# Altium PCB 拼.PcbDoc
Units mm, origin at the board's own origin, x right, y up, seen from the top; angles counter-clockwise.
Board outline 100.51 x 100 mm, 2 copper layers (Top Layer, Bottom Layer); 58 components, 0 nets, 318 pads, 0 vias.
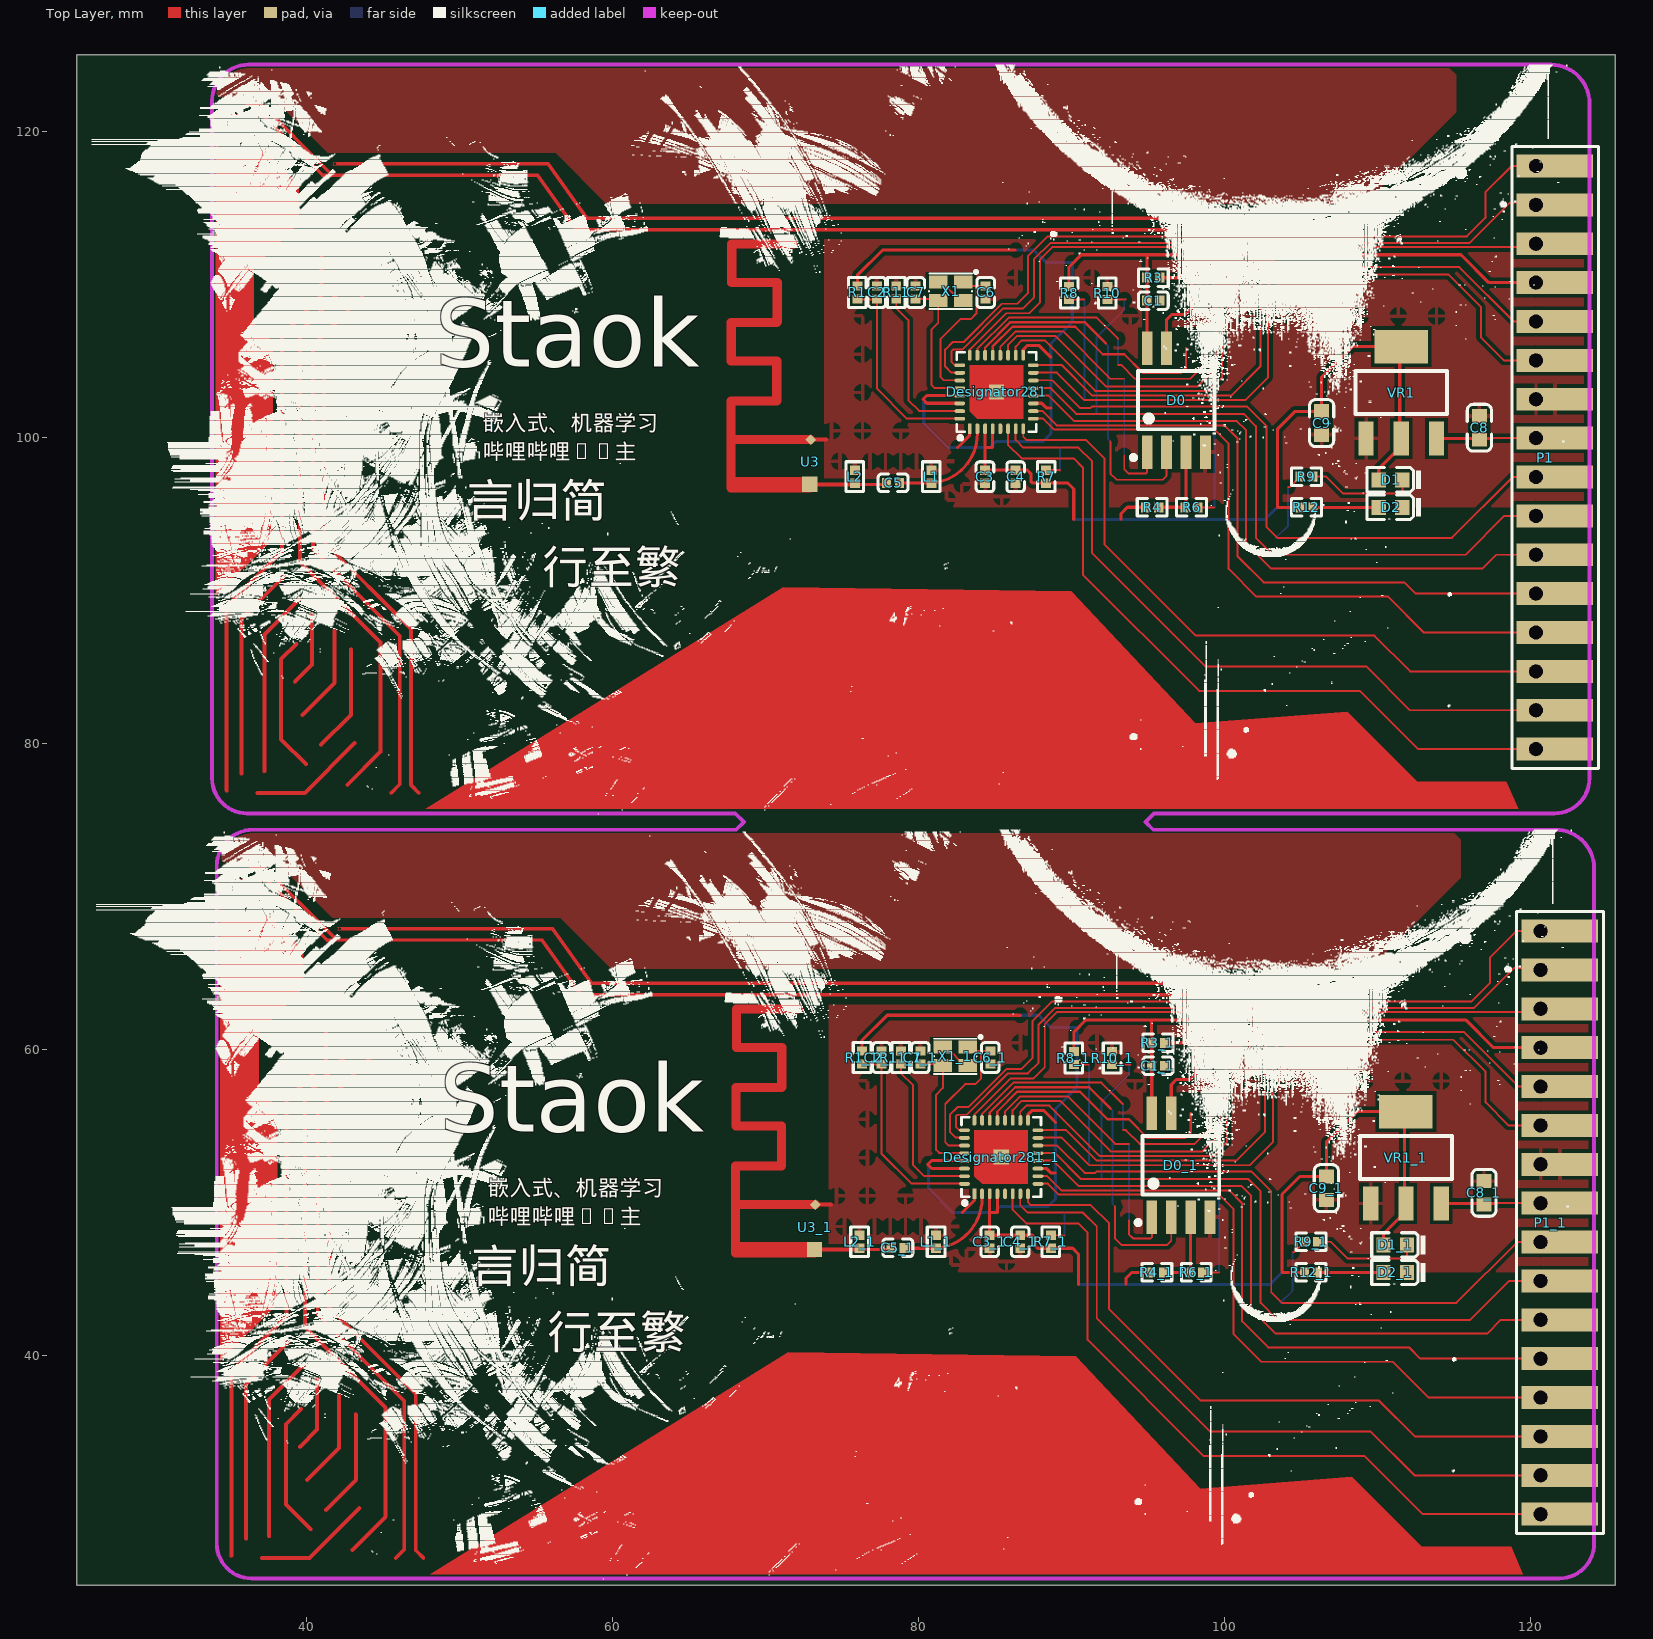
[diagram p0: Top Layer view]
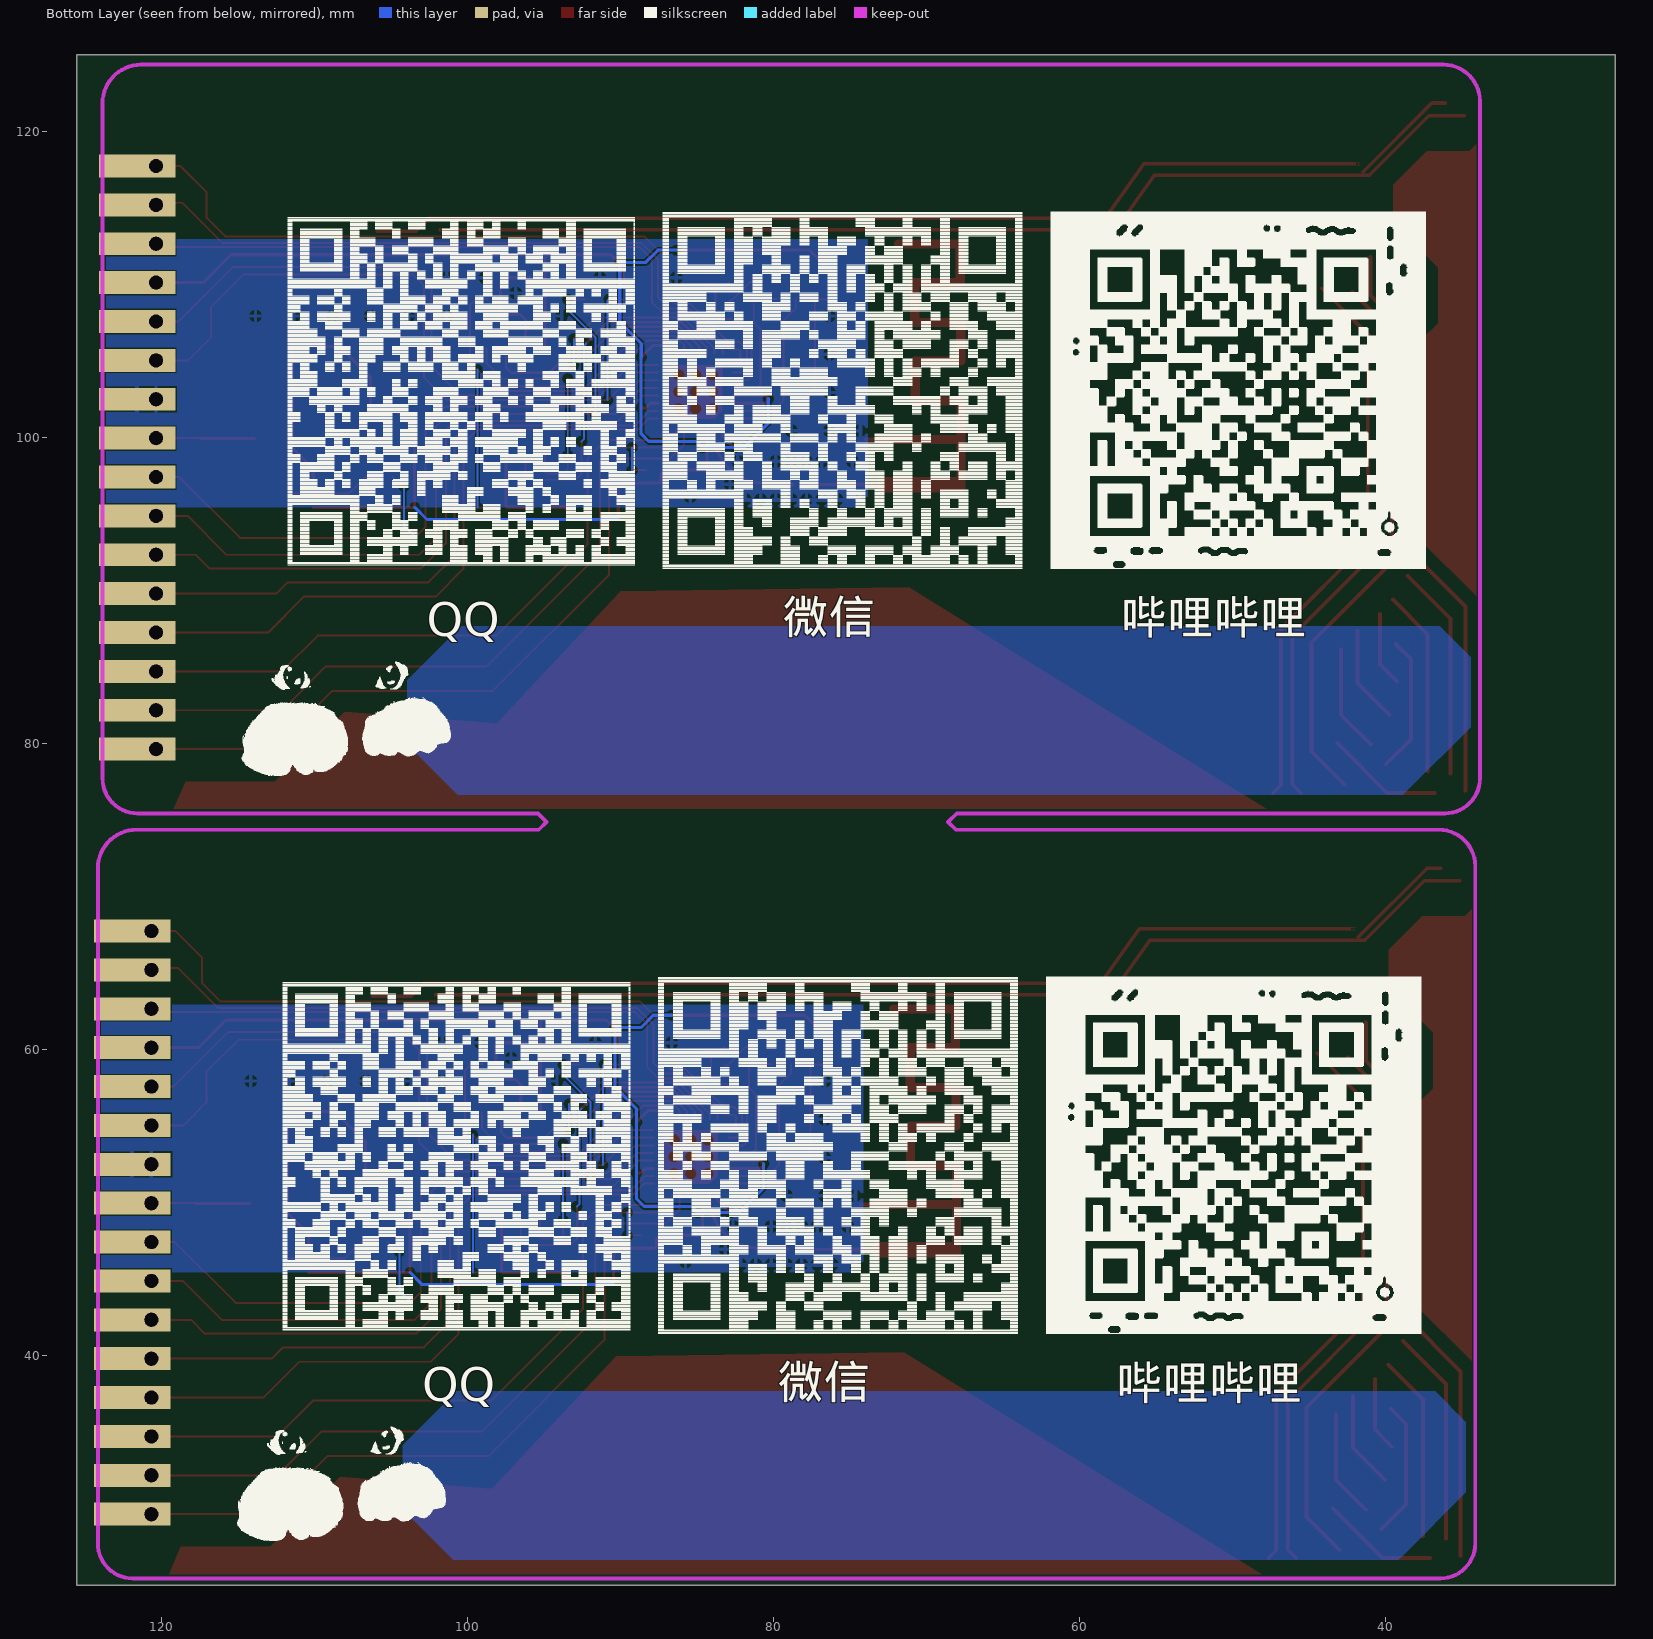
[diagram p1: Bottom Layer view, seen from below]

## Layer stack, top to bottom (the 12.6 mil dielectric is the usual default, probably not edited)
Top Layer: signal copper 0.0356
Dielectric: dielectric 0.32, FR-4, Dk 4.8
Bottom Layer: signal copper 0.0356

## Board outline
25,25 125.508,25 125.508,125 25,125

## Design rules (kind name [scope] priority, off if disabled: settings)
Clearance [All] p1: gap=0.254
PolygonConnect [All] p1: connectstyle=Relief reliefconductorwidth=0.254 reliefentries=4 polygonreliefangle="90 Angle"
RoutingVias [All] p1: holewidth=0.711 width=1.27 viastyle="Through Hole" minholewidth=0.711 minwidth=1.27 maxholewidth=0.711 maxwidth=1.27
SilkscreenOverComponentPads [All] p1: minsilkscreentomaskgap=0.254
SolderMaskExpansion [All] p1: expansion=0.102
Width [All] p1: maxlimit=0.254 minlimit=0.254 preferedwidth=0.254
27 further rules are at their usual default settings.

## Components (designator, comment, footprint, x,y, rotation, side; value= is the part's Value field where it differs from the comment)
C1 "0.1uF" 0402_C 95.334,108.938 r0 top
C1_1 "0.1uF" 0402_C 95.639,58.951 r0 top (schematic designator C1)
C2 "1uF" 0402_C 77.268,109.474 r270 top
C2_1 "1uF" 0402_C 77.573,59.487 r270 top (schematic designator C2)
C3 "0.1uF" 0402_C 84.334,97.438 r90 top
C3_1 "0.1uF" 0402_C 84.639,47.451 r90 top (schematic designator C3)
C4 "10uF" 0402_C 86.334,97.438 r90 top
C4_1 "10uF" 0402_C 86.639,47.451 r90 top (schematic designator C4)
C5 "5.6pF" 0402_C 78.334,97.038 r0 top
C5_1 "5.6pF" 0402_C 78.639,47.051 r0 top (schematic designator C5)
C6 "3.9pF" 0402_C 84.38,109.474 r90 top
C6_1 "3.9pF" 0402_C 84.685,59.487 r90 top (schematic designator C6)
C7 "3.9pF" 0402_C 79.808,109.474 r270 top
C7_1 "3.9pF" 0402_C 80.113,59.487 r270 top (schematic designator C7)
C8 "10uF (106) 10% 10V" 0603_C 116.634,100.638 r270 top
C8_1 "10uF (106) 10% 10V" 0603_C 116.939,50.651 r270 top (schematic designator C8)
C9 "10uF (106) 10% 10V" 0603_C 106.334,100.938 r90 top
C9_1 "10uF (106) 10% 10V" 0603_C 106.639,50.951 r90 top (schematic designator C9)
D0 "W25Q128" SOIC-8_208MIL 96.834,102.438 r0 top
D0_1 "W25Q128" SOIC-8_208MIL 97.139,52.451 r0 top (schematic designator D0)
D1 "红灯 0603" 0603_LED_S1 110.834,97.238 r180 top
D1_1 "红灯 0603" 0603_LED_S1 111.139,47.251 r180 top (schematic designator D1)
D2 "红灯 0603" 0603_LED_S1 110.834,95.438 r180 top
D2_1 "红灯 0603" 0603_LED_S1 111.139,45.451 r180 top (schematic designator D2)
Designator281 "Comment" "QFN32 5x5_L" 85.09,102.972 r0 top
Designator281_1 "Comment" "QFN32 5x5_L" 85.395,52.984 r0 top
L1 "NC" 0402_L 80.834,97.438 r90 top
L1_1 "NC" 0402_L 81.139,47.451 r90 top (schematic designator L1)
L2 "NC" 0402_L 75.834,97.438 r90 top
L2_1 "NC" 0402_L 76.139,47.451 r90 top (schematic designator L2)
P1 "Header 16" HDR1X15 120.334,117.738 r270 top
P1_1 "Header 16" HDR1X15 120.639,67.751 r270 top (schematic designator P1)
R1 "12K" 0402_R 75.998,109.474 r90 top
R1_1 "12K" 0402_R 76.303,59.487 r90 top (schematic designator R1)
R3 "0R/NC" 0402_R 95.334,110.438 r180 top
R3_1 "0R/NC" 0402_R 95.639,60.451 r180 top (schematic designator R3)
R4 "0R/NC" 0402_R 95.259,95.438 r180 top
R4_1 "0R/NC" 0402_R 95.564,45.451 r180 top (schematic designator R4)
R6 "0R/NC" 0402_R 97.834,95.438 r0 top
R6_1 "0R/NC" 0402_R 98.139,45.451 r0 top (schematic designator R6)
R7 "12K" 0402_R 88.334,97.438 r270 top
R7_1 "12K" 0402_R 88.639,47.451 r270 top (schematic designator R7)
R8 "12K" 0402_R 89.834,109.438 r90 top
R8_1 "12K" 0402_R 90.139,59.451 r90 top (schematic designator R8)
R9 "1K" 0402_R 105.334,97.438 r0 top
R9_1 "1K" 0402_R 105.639,47.451 r0 top (schematic designator R9)
R10 "12K" 0402_R 92.334,109.438 r90 top
R10_1 "12K" 0402_R 92.639,59.451 r90 top (schematic designator R10)
R11 "12K" 0402_R 78.538,109.474 r90 top
R11_1 "12K" 0402_R 78.843,59.487 r90 top (schematic designator R11)
R12 "1K" 0402_R 105.334,95.438 r0 top
R12_1 "1K" 0402_R 105.639,45.451 r0 top (schematic designator R12)
U3 "PCB_ANT" BLE-ANT4 72.943,99.858 r90 top
U3_1 "PCB_ANT" BLE-ANT4 73.248,49.871 r90 top (schematic designator U3)
VR1 "AMS1117-3.3" SOT-223 111.534,102.938 r270 top
VR1_1 "AMS1117-3.3" SOT-223 111.839,52.951 r270 top (schematic designator VR1)
X1 "26MHz" SMT_XTAL_2520 82.094,109.474 r180 top
X1_1 "26MHz" SMT_XTAL_2520 82.399,59.487 r180 top (schematic designator X1)

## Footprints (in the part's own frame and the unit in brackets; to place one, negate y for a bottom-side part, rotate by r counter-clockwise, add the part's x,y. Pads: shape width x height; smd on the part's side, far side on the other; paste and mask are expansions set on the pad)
0402_C [mm]
  rect 0.6x0.65 smd: 1(-0.425,0) 2(0.425,0)
  silkscreen extent -0.98,-0.58 0.97,0.58
0402_L [mm]
  rect 0.6x0.65 smd: 1(-0.425,0) 2(0.425,0)
  silkscreen extent -0.97,-0.58 0.98,0.58
0402_R [mm]
  rect 0.6x0.65 smd: 1(-0.425,0) 2(0.425,0)
  silkscreen extent -0.97,-0.57 0.98,0.58
0603_C [mm]
  rect 0.93x0.98 smd: 1(-0.77,0) 2(0.77,0)
  silkscreen extent -1.53,-0.79 1.53,0.79
0603_LED_S1 [mm]
  rect 0.93x0.98 smd: A(0.77,0) K(-0.77,0)
  silkscreen extent -1.98,-0.79 1.53,0.79
BLE-ANT4 [mm]
  rect 0.5x0.5 smd rot 135: 1(0.005,0.005)
  rect 1x1 smd: 2(-2.923,0.052)
  Top Layer lines w0.6: 5.103,2.211 2.545,2.211 2.52,2.236 2.52,5.208 0.005,5.208 ; 5.136,2.211 5.136,5.183 7.65,5.183 7.65,2.211 ; 7.701,2.186 10.267,2.186 10.267,5.157 12.781,5.157 12.781,1.119 ; -3.145,0.052 -3.145,5.208 -2.738,5.208 ; -2.738,0.005 -2.738,0.052 -2.738,5.208 ; 0.005,0.005 0.005,5.208 ; -2.738,5.208 0.005,5.208
HDR1X15 [mm]
  rect 1.5x5 smd: 1(0,1.24) 2(2.54,1.24) 3(5.08,1.24) 4(7.62,1.24) 5(10.16,1.24) 6(12.7,1.24) 7(15.24,1.24) 8(17.78,1.24) 9(20.32,1.24) 10(22.86,1.24) 11(25.4,1.24) 12(27.94,1.24) 13(30.48,1.24) 14(33.02,1.24) 15(35.56,1.24) 16(38.1,1.24)
  rect 1.5x5 smd far side: 1(0,1.24) 2(2.54,1.24) 3(5.08,1.24) 4(7.62,1.24) 5(10.16,1.24) 6(12.7,1.24) 7(15.24,1.24) 8(17.78,1.24) 9(20.32,1.24) 10(22.86,1.24) 11(25.4,1.24) 12(27.94,1.24) 13(30.48,1.24) 14(33.02,1.24) 15(35.56,1.24) 16(38.1,1.24)
  round 1.5 hole 0.9 slot 0.9 at 0 deg: 1(0,0) 2(2.54,0) 3(5.08,0) 4(7.62,0) 5(10.16,0) 6(12.7,0) 7(15.24,0) 8(17.78,0) 9(20.32,0) 10(22.86,0) 11(25.4,0) 12(27.94,0) 13(30.48,0) 14(33.02,0) 15(35.56,0) 16(38.1,0)
  silkscreen extent -1.27,-1.57 39.37,4.1
"QFN32 5x5_L" [mm] "32脚，长x宽x"
  rect 0.25x0.7 smd: 1(-1.751,-2.4)
  oval 0.25x0.7 smd: 2(-1.25,-2.4) 3(-0.75,-2.4) 4(-0.25,-2.4) 5(0.25,-2.4) 6(0.75,-2.4) 7(1.25,-2.4) 8(1.75,-2.4) 17(1.75,2.4) 18(1.25,2.4) 19(0.75,2.4) 20(0.25,2.4) 21(-0.25,2.4) 22(-0.75,2.4) 23(-1.25,2.4) 24(-1.75,2.4)
  oval 0.7x0.25 smd: 9(2.4,-1.75) 10(2.4,-1.25) 11(2.4,-0.75) 12(2.4,-0.25) 13(2.4,0.25) 14(2.4,0.75) 15(2.4,1.25) 16(2.4,1.75) 25(-2.4,1.75) 26(-2.4,1.25) 27(-2.4,0.75) 28(-2.4,0.25) 29(-2.4,-0.25) 30(-2.4,-0.75) 31(-2.4,-1.25) 32(-2.4,-1.75)
  rect 1x1 smd: 33(0,0)
  Top Layer region: -1.75,1.75 1.75,1.75 1.75,-1.75 -1.25,-1.75 -1.75,-1.25
  silkscreen extent -2.6,-3.12 2.6,2.6, body extent -2.5,-2.5 2.5,2.5, height 0.93
SMT_XTAL_2520 [mm]
  rect 1.2x0.85 smd: 1(-0.812,-0.676) 2(0.813,-0.676) 3(0.813,0.524) 4(-0.812,0.524)
  silkscreen extent -1.75,-1.44 1.41,1.07
SOIC-8_208MIL [mm]
  rect 0.7x2.199 smd: 1(-1.905,-3.4) 2(-0.635,-3.4) 3(0.635,-3.4) 4(1.905,-3.4) 7(-0.635,3.4) 8(-1.905,3.4)
  rect 0.7x2.199 on Mech1: 5(1.905,3.4) 6(0.635,3.4)
  silkscreen extent -2.95,-3.9 2.5,1.9
SOT-223 [mm]
  rect 2.2x1 smd: 1(3,-2.3) 2(3,0) 3(3,2.3)
  rect 2.2x3.5 smd: 2(-3,0)
  silkscreen extent -1.4,-3 1.4,3

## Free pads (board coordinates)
  round 0 smd: 50(38.399,94.144) 50(38.704,44.156) 51(35.757,85.077) 51(36.062,35.09) 52(37.256,84.268) 52(37.561,34.281) 53(38.348,82.449) 53(38.653,32.462) 54(40.38,86.02) 54(40.685,36.033) 55(41.828,84.194) 55(42.133,34.207) 56(42.92,82.633) 56(43.225,32.646) 57(40.428,77.307) 57(40.732,27.32) 58(39.593,92.397) 58(39.897,42.409) 59(40.431,92.746) 59(40.736,42.759) 60(43.553,90.775) 60(43.858,40.787) 63(38.907,119.924) 63(39.212,69.937) 64(66.593,113.574) 64(66.898,63.587) 65(72.943,114.336) 65(73.248,64.349)

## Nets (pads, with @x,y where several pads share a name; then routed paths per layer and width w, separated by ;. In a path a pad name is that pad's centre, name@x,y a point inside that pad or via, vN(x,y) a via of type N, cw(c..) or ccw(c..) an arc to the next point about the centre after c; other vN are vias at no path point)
pads on no net: C1.1 C1.2 C1_1.1 C1_1.2 C2.1 C2.2 C2_1.1 C2_1.2 C3.1 C3.2 C3_1.1 C3_1.2 C4.1 C4.2 C4_1.1 C4_1.2 C5.1 C5.2 C5_1.1 C5_1.2 C6.1 C6.2 C6_1.1 C6_1.2 C7.1 C7.2 C7_1.1 C7_1.2 C8.1 C8.2 C8_1.1 C8_1.2 C9.1 C9.2 C9_1.1 C9_1.2 D0.1 D0.2 D0.3 D0.4 D0.5 D0.6 D0.7 D0.8 D0_1.1 D0_1.2 D0_1.3 D0_1.4 D0_1.5 D0_1.6 D0_1.7 D0_1.8 D1.A D1.K D1_1.A D1_1.K D2.A D2.K D2_1.A D2_1.K Designator281.1 Designator281.2 Designator281.3 Designator281.4 Designator281.5 Designator281.6 Designator281.7 Designator281.8 Designator281.9 Designator281.10 Designator281.11 Designator281.12 Designator281.13 Designator281.14 Designator281.15 Designator281.16 Designator281.17 Designator281.18 Designator281.19 Designator281.20 Designator281.21 Designator281.22 Designator281.23 Designator281.24 Designator281.25 Designator281.26 Designator281.27 Designator281.28 Designator281.29 Designator281.30 Designator281.31 Designator281.32 Designator281.33 Designator281_1.1 Designator281_1.2 Designator281_1.3 Designator281_1.4 Designator281_1.5 Designator281_1.6 Designator281_1.7 Designator281_1.8 Designator281_1.9 Designator281_1.10 Designator281_1.11 Designator281_1.12 Designator281_1.13 Designator281_1.14 Designator281_1.15 Designator281_1.16 Designator281_1.17 Designator281_1.18 Designator281_1.19 Designator281_1.20 Designator281_1.21 Designator281_1.22 Designator281_1.23 Designator281_1.24 Designator281_1.25 Designator281_1.26 Designator281_1.27 Designator281_1.28 Designator281_1.29 Designator281_1.30 Designator281_1.31 Designator281_1.32 Designator281_1.33 L1.1 L1.2 L1_1.1 L1_1.2 L2.1 L2.2 L2_1.1 L2_1.2 P1.1 P1.2 P1.3 P1.4 P1.5 P1.6 P1.7 P1.8 P1.9 P1.10 P1.11 P1.12 P1.13 P1.14 P1.15 P1.16 P1_1.1 P1_1.2 P1_1.3 P1_1.4 P1_1.5 P1_1.6 P1_1.7 P1_1.8 P1_1.9 P1_1.10 P1_1.11 P1_1.12 P1_1.13 P1_1.14 P1_1.15 P1_1.16 R1.1 R1.2 R1_1.1 R1_1.2 R3.1 R3.2 R3_1.1 R3_1.2 R4.1 R4.2 R4_1.1 R4_1.2 R6.1 R6.2 R6_1.1 R6_1.2 R7.1 R7.2 R7_1.1 R7_1.2 R8.1 R8.2 R8_1.1 R8_1.2 R9.1 R9.2 R9_1.1 R9_1.2 R10.1 R10.2 R10_1.1 R10_1.2 R11.1 R11.2 R11_1.1 R11_1.2 R12.1 R12.2 R12_1.1 R12_1.2 U3.1 U3.2 U3_1.1 U3_1.2 VR1.1 VR1.2 VR1.3 VR1_1.1 VR1_1.2 VR1_1.3 X1.1 X1.2 X1.3 X1.4 X1_1.1 X1_1.2 X1_1.3 X1_1.4
copper on no net: | length 1957.9
  Top Layer w0.127: 76.334,109.013 77.268,109.013 ; 76.639,59.026 77.573,59.026 ; 77.268,109.049 77.268,109.013 ; 77.573,59.062 77.573,59.026 ; 78.538,109.049 78.538,108.458 79.334,107.662 79.334,102.438 80.034,101.738 82.634,101.738 ; 78.843,59.062 78.843,58.471 79.639,57.675 79.639,52.451 80.339,51.751 82.939,51.751 ; 79.808,109.049 81.183,109.049 81.281,108.95 81.281,107.493 80.834,107.045 80.834,103.438 81.034,103.238 82.634,103.238 ; 80.113,59.062 81.487,59.062 81.586,58.963 81.586,57.505 81.139,57.058 81.139,53.451 81.339,53.251 82.939,53.251 ; 81.281,110.15 81.522,110.15 82.722,108.95 82.906,108.95 ; 81.586,60.163 81.826,60.163 83.026,58.963 83.211,58.963 ; 82.634,101.238 79.234,101.238 77.268,103.204 77.268,109.013 ; 82.634,103.738 81.634,103.738 81.434,103.938 81.434,106.438 82.734,107.738 83.406,107.738 83.769,108.101 83.769,109.899 ; 82.634,104.238 82.134,104.238 81.734,104.638 81.734,105.738 82.234,106.238 82.939,106.238 85.439,108.738 86.434,108.738 87.134,109.438 87.134,111.838 88.434,113.138 115.818,113.138 117.034,114.354 117.034,116.018 118.754,117.738 120.334,117.738 121.574,117.738 ; 82.634,104.738 82.334,104.738 82.134,104.938 82.134,105.638 82.234,105.738 82.834,105.738 85.534,108.438 86.834,108.438 87.534,109.138 87.534,111.633 88.618,112.718 115.993,112.718 118.613,115.338 121.434,115.338 121.574,115.198 ; 82.906,110.15 83.158,109.899 83.769,109.899 ; 82.939,51.251 79.539,51.251 77.573,53.217 77.573,59.026 ; 82.939,53.751 81.938,53.751 81.739,53.951 81.739,56.451 83.039,57.751 83.711,57.751 84.074,58.114 84.074,59.912 ; 82.939,54.251 82.439,54.251 82.039,54.651 82.039,55.751 82.539,56.251 83.244,56.251 85.743,58.751 86.739,58.751 87.439,59.451 87.439,61.851 88.739,63.151 116.123,63.151 117.339,64.366 117.339,66.031 119.059,67.751 120.639,67.751 121.879,67.751 ; 82.939,54.751 82.639,54.751 82.439,54.951 82.439,55.651 82.539,55.751 83.139,55.751 85.839,58.451 87.139,58.451 87.839,59.151 87.839,61.646 88.923,62.73 116.297,62.73 118.918,65.351 121.739,65.351 121.879,65.211 ; 83.211,60.163 83.462,59.912 84.074,59.912 ; 83.334,105.438 83.334,105.738 85.713,108.117 87.213,108.117 87.934,108.838 87.934,111.638 88.734,112.438 121.354,112.438 121.574,112.658 ; 83.639,55.451 83.639,55.751 86.018,58.13 87.518,58.13 88.239,58.851 88.239,61.651 89.039,62.451 121.659,62.451 121.879,62.671 ; 83.834,105.438 83.834,105.782 85.89,107.838 91.634,107.838 93.034,106.438 ; 84.139,55.451 84.139,55.795 86.195,57.851 91.939,57.851 93.339,56.451 ; 84.38,109.899 83.769,109.899 ; 84.685,59.912 84.074,59.912 ; 85.334,105.438 85.334,105.933 86.339,106.938 89.434,106.938 92.534,103.838 93.434,103.838 ; 85.639,55.451 85.639,55.946 86.644,56.951 89.739,56.951 92.839,53.851 93.739,53.851 ; 85.834,100.538 85.834,99.538 86.734,98.638 90.134,98.638 90.734,98.038 90.734,91.031 98.327,83.438 108.834,83.438 112.634,79.638 120.334,79.638 121.574,79.638 ; 85.834,105.438 85.834,106.038 86.434,106.638 88.934,106.638 92.234,103.338 98.234,103.338 99.334,104.438 ; 86.139,50.551 86.139,49.551 87.039,48.651 90.439,48.651 91.039,48.051 91.039,41.044 98.632,33.451 109.139,33.451 112.939,29.651 120.639,29.651 121.879,29.651 ; 86.139,55.451 86.139,56.051 86.739,56.651 89.239,56.651 92.539,53.351 98.539,53.351 99.639,54.451 ; 86.334,100.538 86.334,99.838 86.834,99.338 89.234,99.338 90.434,99.338 91.334,98.438 91.334,92.438 98.734,85.038 109.234,85.038 112.094,82.178 120.334,82.178 121.574,82.178 ; 86.334,105.438 86.334,105.938 86.734,106.338 88.234,106.338 91.534,103.038 98.934,103.038 99.834,103.938 99.834,108.638 99.434,109.038 98.659,109.038 ; 86.639,50.551 86.639,49.851 87.139,49.351 89.539,49.351 90.739,49.351 91.639,48.451 91.639,42.451 99.039,35.051 109.539,35.051 112.399,32.191 120.639,32.191 121.879,32.191 ; 86.639,55.451 86.639,55.951 87.039,56.351 88.539,56.351 91.839,53.051 99.239,53.051 100.139,53.951 100.139,58.651 99.739,59.051 98.964,59.051 ; 86.834,100.538 86.834,100.038 87.034,99.838 90.934,99.838 92.134,98.638 92.134,93.038 98.114,87.058 109.774,87.058 112.114,84.718 120.334,84.718 121.574,84.718 ; 87.139,50.551 87.139,50.051 87.339,49.851 91.239,49.851 92.439,48.651 92.439,43.051 98.419,37.071 110.079,37.071 112.419,34.731 120.639,34.731 121.879,34.731 ; 87.534,101.238 88.134,101.238 88.858,100.513 99.334,100.513 100.258,99.589 100.258,91.413 102.074,89.598 110.674,89.598 113.014,87.258 120.334,87.258 121.574,87.258 ; 87.534,101.738 88.075,101.738 89.02,100.793 99.979,100.793 100.834,99.938 100.834,92.238 102.534,90.538 111.734,90.538 112.474,89.798 120.334,89.798 121.574,89.798 ; 87.534,102.738 88.493,102.738 90.159,101.072 100.8,101.072 101.398,100.474 101.398,93.074 103.034,91.438 116.834,91.438 117.734,92.338 120.334,92.338 121.574,92.338 ; 87.534,103.238 88.588,103.238 90.288,101.538 91.634,101.538 101.234,101.538 102.034,100.738 102.034,93.438 103.134,92.338 115.734,92.338 118.274,94.878 120.334,94.878 121.574,94.878 ; 87.534,103.738 88.734,103.738 90.534,101.938 91.234,101.938 91.334,102.038 101.434,102.038 102.734,100.738 102.734,94.138 103.434,93.438 114.834,93.438 118.814,97.418 120.334,97.418 121.574,97.418 ; 87.534,104.238 89.034,104.238 90.834,102.438 101.334,102.438 102.834,103.938 102.834,109.938 103.534,110.638 114.634,110.638 116.734,108.538 116.734,106.538 118.234,105.038 120.334,105.038 121.574,105.038 ; 87.534,104.738 89.334,104.738 91.334,102.738 100.434,102.738 102.334,104.638 102.334,110.145 103.327,111.138 115.334,111.138 118.894,107.578 120.334,107.578 121.574,107.578 ; 87.839,51.251 88.439,51.251 89.163,50.526 99.639,50.526 100.563,49.601 100.563,41.426 102.379,39.611 110.979,39.611 113.319,37.271 120.639,37.271 121.879,37.271 ; 87.839,51.751 88.38,51.751 89.325,50.806 100.284,50.806 101.139,49.951 101.139,42.251 102.839,40.551 112.039,40.551 112.779,39.811 120.639,39.811 121.879,39.811 ; 87.839,52.751 88.798,52.751 90.463,51.085 101.105,51.085 101.703,50.487 101.703,43.087 103.339,41.451 117.139,41.451 118.039,42.351 120.639,42.351 121.879,42.351 ; 87.839,53.251 88.893,53.251 90.593,51.551 91.939,51.551 101.539,51.551 102.339,50.751 102.339,43.451 103.439,42.351 116.039,42.351 118.579,44.891 120.639,44.891 121.879,44.891 ; 87.839,53.751 89.039,53.751 90.839,51.951 91.539,51.951 91.639,52.051 101.739,52.051 103.039,50.751 103.039,44.151 103.739,43.451 115.139,43.451 119.119,47.431 120.639,47.431 121.879,47.431 ; 87.839,54.251 89.339,54.251 91.139,52.451 101.639,52.451 103.139,53.951 103.139,59.951 103.839,60.651 114.939,60.651 117.039,58.551 117.039,56.551 118.539,55.051 120.639,55.051 121.879,55.051 ; 87.839,54.751 89.638,54.751 91.639,52.751 100.739,52.751 102.639,54.651 102.639,60.158 103.632,61.151 115.639,61.151 119.199,57.591 120.639,57.591 121.879,57.591 ; 88.334,97.863 89.209,97.863 89.234,97.838 ; 88.639,47.876 89.514,47.876 89.539,47.851 ; 89.834,109.013 90.809,109.013 90.734,109.038 ; 90.139,59.026 91.114,59.026 91.039,59.051 ; 92.334,109.013 93.434,109.013 93.509,109.013 93.534,109.038 ; 92.534,99.738 92.534,97.638 92.934,97.238 95.934,97.238 96.199,97.503 96.199,99.038 ; 92.639,59.026 93.739,59.026 93.814,59.026 93.839,59.051 ; 92.839,49.751 92.839,47.651 93.239,47.251 96.239,47.251 96.504,47.516 96.504,49.051 ; 93.034,104.738 93.234,104.738 94.134,103.838 97.734,103.838 98.739,104.843 98.739,105.838 ; 93.339,54.751 93.539,54.751 94.439,53.851 98.039,53.851 99.044,54.856 99.044,55.851 ; 93.434,98.838 93.434,97.938 93.734,97.638 94.834,97.638 94.929,97.733 94.929,99.038 ; 93.739,48.851 93.739,47.951 94.039,47.651 95.139,47.651 95.234,47.746 95.234,49.051 ; 98.259,95.438 99.334,95.438 ; 98.564,45.451 99.639,45.451 ; 104.159,96.763 104.234,96.763 104.909,97.438 ; 104.464,46.776 104.539,46.776 105.214,47.451 ; 105.759,97.438 106.634,97.438 107.734,96.338 111.434,96.338 111.604,96.508 111.604,97.238 ; 106.064,47.451 106.939,47.451 108.039,46.351 111.739,46.351 111.909,46.521 111.909,47.251 ; 113.834,99.938 113.854,99.958 117.454,99.958 120.334,99.958 121.574,99.958 ; 114.139,49.951 114.159,49.971 117.759,49.971 120.639,49.971 121.879,49.971 ; 120.334,102.498 121.574,102.498 ; 120.639,52.511 121.879,52.511
  Top Layer w0.152: 84.334,105.438 84.334,105.869 86.003,107.538 90.834,107.538 92.234,106.138 ; 84.639,55.451 84.639,55.882 86.308,57.551 91.139,57.551 92.539,56.151 ; 84.834,105.438 84.834,105.938 86.129,107.233 90.239,107.233 92.034,105.438 93.434,105.438 94.634,104.238 97.134,104.238 97.469,104.573 97.469,105.838 ; 85.139,55.451 85.139,55.951 86.434,57.246 90.544,57.246 92.339,55.451 93.739,55.451 94.939,54.251 97.439,54.251 97.774,54.586 97.774,55.851
  Top Layer w0.2: 75.909,96.938 77.909,96.938 ; 76.214,46.951 78.214,46.951 ; 78.834,97.013 80.834,97.013 ccw(c80.571,100.276) 83.834,100.538 ; 79.139,47.026 81.139,47.026 ccw(c80.876,50.288) 84.139,50.551 ; 82.534,99.338 83.334,100.138 83.334,100.538 ; 82.634,102.238 80.534,102.238 80.284,102.488 80.534,102.738 82.634,102.738 ; 82.839,49.351 83.639,50.151 83.639,50.551 ; 82.939,52.251 80.839,52.251 80.589,52.501 80.839,52.751 82.939,52.751 ; 84.334,100.538 84.334,99.338 ; 84.639,50.551 84.639,49.351 ; 84.834,100.538 84.834,99.338 84.634,99.338 84.334,99.338 ; 85.139,50.551 85.139,49.351 84.939,49.351 84.639,49.351 ; 86.834,105.438 86.834,105.738 87.118,106.022 87.85,106.022 88.634,105.238 ; 87.139,55.451 87.139,55.751 87.423,56.035 88.155,56.035 88.939,55.251 ; 87.534,102.238 88.034,102.238 88.334,101.938 88.634,101.938 ; 87.839,52.251 88.339,52.251 88.639,51.951 88.939,51.951 ; 90.134,94.638 90.134,96.638 89.759,97.013 88.334,97.013 87.459,97.013 87.334,97.138 87.334,97.638 87.109,97.863 86.334,97.863 84.334,97.863 84.334,99.338 ; 90.439,44.651 90.439,46.651 90.064,47.026 88.639,47.026 87.764,47.026 87.639,47.151 87.639,47.651 87.414,47.876 86.639,47.876 84.639,47.876 84.639,49.351 ; 104.909,95.438 103.434,95.438 103.434,100.538 104.604,101.708 106.334,101.708 ; 105.214,45.451 103.739,45.451 103.739,50.551 104.909,51.721 106.639,51.721 ; 105.759,95.438 110.064,95.438 ; 106.064,45.451 110.369,45.451
  Top Layer w0.203: 75.998,109.899 75.998,110.602 77.634,112.238 86.334,112.238 ; 76.303,59.912 76.303,60.615 77.939,62.251 86.639,62.251 ; 89.834,109.863 89.834,111.138 90.634,111.938 115.434,111.938 117.254,110.118 121.574,110.118 ; 90.139,59.876 90.139,61.151 90.939,61.951 115.739,61.951 117.559,60.131 121.879,60.131 ; 93.234,94.638 93.234,95.038 93.634,95.438 94.834,95.438 ; 93.539,44.651 93.539,45.051 93.939,45.451 95.139,45.451 ; 94.909,110.438 94.909,111.913 94.934,111.938 ; 94.929,105.838 94.929,110.438 ; 95.214,60.451 95.214,61.926 95.239,61.951 ; 95.234,55.851 95.234,60.451 ; 95.684,95.438 97.409,95.438 97.469,95.498 97.469,99.038 ; 95.859,110.438 97.634,110.438 97.834,110.238 97.834,108.438 97.434,108.038 96.534,108.038 96.199,107.703 96.199,105.838 ; 95.988,45.451 97.714,45.451 97.774,45.511 97.774,49.051 ; 96.164,60.451 97.939,60.451 98.139,60.251 98.139,58.451 97.739,58.051 96.839,58.051 96.504,57.716 96.504,55.851 ; 106.334,101.708 106.334,103.938 108.334,105.938 111.434,105.938 111.434,99.938 ; 106.639,51.721 106.639,53.951 108.639,55.951 111.739,55.951 111.739,49.951 ; 110.064,97.238 110.064,97.968 111.534,99.438 111.534,99.938 ; 110.369,47.251 110.369,47.981 111.839,49.451 111.839,49.951 ; 113.934,99.938 117.434,99.938 117.454,99.958 ; 114.239,49.951 117.739,49.951 117.759,49.971
  Top Layer w0.254: 72.891,96.935 75.756,96.935 75.834,97.013 75.909,96.938 ; 72.938,99.863 73.954,99.863 73.959,99.858 ; 73.196,46.948 76.06,46.948 76.139,47.026 76.214,46.951 ; 73.243,49.876 74.259,49.876 74.264,49.871 ; 78.759,96.938 78.834,97.013 ; 79.064,46.951 79.139,47.026
  Bottom Layer w0.127: 89.234,97.838 89.234,99.338 ; 89.539,47.851 89.539,49.351 ; 90.734,109.038 90.834,108.938 90.834,102.438 ; 91.039,59.051 91.139,58.951 91.139,52.451 ; 91.634,101.538 91.634,106.538 93.434,108.338 93.434,109.013 ; 91.939,51.551 91.939,56.551 93.739,58.351 93.739,59.026 ; 92.234,106.138 92.368,106.004 92.368,99.904 92.534,99.738 ; 92.539,56.151 92.673,56.017 92.673,49.917 92.839,49.751 ; 93.034,104.738 93.034,106.438 ; 93.339,54.751 93.339,56.451 ; 93.434,98.838 93.434,103.838 ; 93.739,48.851 93.739,53.851 ; 99.334,95.438 99.334,104.438 ; 99.639,45.451 99.639,54.451 ; 103.334,93.438 104.134,94.238 104.134,96.763 ; 103.639,43.451 104.439,44.251 104.439,46.776
  Bottom Layer w0.2: 80.334,102.538 80.334,100.938 81.934,99.338 82.534,99.338 84.634,99.338 85.034,99.738 88.134,99.738 88.634,100.238 88.634,101.938 88.634,105.238 ; 80.639,52.551 80.639,50.951 82.239,49.351 82.839,49.351 84.939,49.351 85.339,49.751 88.439,49.751 88.939,50.251 88.939,51.951 88.939,55.251 ; 90.134,94.638 93.234,94.638 102.634,94.638 103.434,95.438 ; 90.439,44.651 93.539,44.651 102.939,44.651 103.739,45.451
  Bottom Layer w0.203: 86.334,112.238 87.534,112.238 88.334,111.438 90.034,111.438 90.034,107.538 88.634,106.138 88.634,105.238 ; 86.639,62.251 87.839,62.251 88.639,61.451 90.339,61.451 90.339,57.551 88.939,56.151 88.939,55.251

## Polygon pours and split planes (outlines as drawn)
no net on Top Layer "Top Layer-GND" (solid, pour order 2): 74.139,62.951 74.139,45.451 124.139,45.451 124.139,62.951
no net on Top Layer "Top Layer-No Net" (solid, pour order 8): 36.22,74.422 36.093,74.422 ccw(c36.093,72.542) 34.214,72.542 34.493,72.263 37.44,72.263 38.049,72.263 41.605,68.707 41.707,68.605 56.337,68.605 56.591,68.605 59.868,65.329 59.919,65.278 103.657,65.278 109.449,65.278 113.589,69.418 115.418,71.247 115.418,73.609 115.418,73.711 114.732,74.397 114.681,74.346 110.16,74.346
no net on Top Layer "Top Layer-GND" (solid, pour order 2): 73.834,112.938 73.834,95.438 123.834,95.438 123.834,112.938
no net on Top Layer "Top Layer-No Net" (solid, pour order 8): 35.916,124.409 35.789,124.409 ccw(c35.789,122.53) 33.909,122.53 34.188,122.25 37.135,122.25 37.744,122.25 41.3,118.694 41.402,118.593 56.032,118.593 56.286,118.593 59.563,115.316 59.614,115.265 103.353,115.265 109.144,115.265 113.284,119.405 115.113,121.234 115.113,123.596 115.113,123.698 114.427,124.384 114.376,124.333 109.855,124.333
no net on Bottom Layer "Bottom Layer-GND" (solid, pour order 4): 74.139,62.951 124.139,62.951 124.139,45.451 74.139,45.451
no net on Bottom Layer "Top Layer-No Net" (solid, pour order 10): 34.747,35.585 34.747,31.09 38.887,26.949 39.167,26.67 99.924,26.67 100.914,26.67 103.835,29.591 104.216,29.972 104.216,33.452 104.216,34.163 102.286,36.093 100.711,37.668 36.957,37.668 36.754,37.668 34.747,35.662
no net on Bottom Layer "Bottom Layer-GND" (solid, pour order 4): 73.834,112.938 123.834,112.938 123.834,95.438 73.834,95.438
no net on Bottom Layer "Top Layer-No Net" (solid, pour order 10): 34.442,85.573 34.442,81.077 38.583,76.937 38.862,76.657 99.619,76.657 100.609,76.657 103.53,79.578 103.911,79.959 103.911,83.439 103.911,84.15 101.981,86.081 100.406,87.655 36.652,87.655 36.449,87.655 34.442,85.649

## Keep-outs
Keep-Out Layer:
  lines w0.254: 33.834,77.732 ccw(c36.128,77.732) 36.128,75.438 ; 33.834,121.974 cw(c36.218,121.974) 36.218,124.358 ; 34.139,27.745 ccw(c36.433,27.745) 36.433,25.451 ; 34.139,71.987 cw(c36.523,71.987) 36.523,74.371 ; 121.304,124.358 cw(c121.304,121.829) 123.834,121.829 ; 121.539,75.438 ccw(c121.539,77.732) 123.834,77.732 ; 121.609,74.371 cw(c121.609,71.842) 124.139,71.842 ; 121.844,25.451 ccw(c121.844,27.745) 124.139,27.745

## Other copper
Top Layer:
  drawing of 32 lines, arcs and shapes, not listed

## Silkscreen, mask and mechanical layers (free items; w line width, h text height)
Top Overlay:
  drawing of 30012 lines, arcs and shapes, not listed
  text "Staok" at 48.412,103.149 h7.62
  text "嵌入式、机器学习" at 51.537,100.076 h1.78
  text "哔哩哔哩UP主" at 51.537,98.222 h1.78
  text "言归简" at 50.504,94.057 h3.81
  text "行至繁" at 55.386,89.717 h3.81
  text "Staok" at 48.717,53.162 h7.62
  text "嵌入式、机器学习" at 51.841,50.089 h1.78
  text "哔哩哔哩UP主" at 51.841,48.235 h1.78
  text "言归简" at 50.809,44.07 h3.81
  text "行至繁" at 55.691,39.73 h3.81
Bottom Overlay:
  drawing of 21384 lines, arcs and shapes, not listed
  text "微信" at 79.426,86.457 h3.81
  text "哔哩哔哩" at 57.302,86.411 h3.81
  text "QQ" at 102.64,86.277 h3.81
  text "微信" at 79.731,36.469 h3.81
  text "哔哩哔哩" at 57.607,36.424 h3.81
  text "QQ" at 102.945,36.29 h3.81
Top Solder:
  drawing of 28 lines, arcs and shapes, not listed
Bottom Solder:
  lines w0.254: 35.204,82.804 39.472,82.804 40.996,81.28 58.039,81.28 59.233,82.474 ; 35.509,32.817 39.776,32.817 41.3,31.293 58.344,31.293 59.538,32.487 ; 36.297,81.788 39.395,78.689 58.115,78.689 61.214,81.788 98.298,81.788 ; 36.601,31.801 39.7,28.702 58.42,28.702 61.519,31.801 98.603,31.801 ; 46.965,82.093 56.566,82.093 57.683,83.21 68.656,83.21 ; 47.269,32.106 56.871,32.106 57.988,33.223 68.961,33.223 ; 71.768,83.299 72.492,82.575 100.432,82.575 ; 72.072,33.312 72.796,32.588 100.736,32.588
Mechanical 15:
  lines w0.003: 76.935,102.413 76.986,102.463 ; 77.24,52.425 77.291,52.476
